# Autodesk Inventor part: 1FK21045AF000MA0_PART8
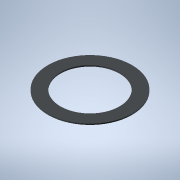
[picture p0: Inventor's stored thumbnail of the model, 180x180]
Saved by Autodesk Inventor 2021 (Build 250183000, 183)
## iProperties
Created: 2025-04
Part Number: 1FK21045AF000MA0_PART8
Material: Generic
Catalog Web Link: www.3dfindit.com
Description: -Servo synchronous motor
Document SubType Name: Modeling
Designer: psAdmin
Mass: 0.27214 g
Surface Area: 11.8752 cm^2
Volume: 0.27214 cm^3
Density: 1 g/cm^3
Appearance: PSOLRGB-212-217-219
Category: PARTsolutions
Title: 1FK21045AF000MA0_PART8
Author: Cadenas PARTsolutions
Comments: Servo synchronous motor
Sending System: PARTsolutions
Preprocessor: ST-DEVELOPER v19.3
PSOL_IDENT_0: {$CADENAS_DATA/23d-libs/siemens_ag/_cat_/8b/0a/1fk21045af000ma0.prj},213 {VTYP=3D},{NB=1FK21045AF000
PSOL_IDENT_1: MA0_PART8},{LINA=1FK21045AF000MA0_PART8},{NN=1FK21045AF000MA0_PART8},{NOPRJ=TRUE},{DATE=19.08.2025 1
PSOL_IDENT_2: 4:00:48},{GEOMDATE=30.07.2025 02:00:28},{VERSION=},{LINEID=10},{WBVAR=},{WBNUMERIC=}  {NB=1FK21045AF
PSOL_IDENT_3: 000MA0_PART8},{LINA=1FK21045AF000MA0_PART8},{KT=DUMMY},{PREVIEW=../../../_pool_/a9/69/p_d211_xx_0081
PSOL_IDENT_4: 8j.png},{DESCSHORT=SIMOTICS S-1FK2 HD, SINAMICS S210 3AC 400V-480V, 2.4 Nm, 3000 rpm},{DESCLONG=SIMO
PSOL_IDENT_5: TICS S-1FK2 HD servo motor M0=2.4 Nm; PN = 0.75 kW at nN=3000 rpm (380-480 V); PN = 0.375 kW at nN=1
PSOL_IDENT_6: 500 rpm (200-240 V); degree of protection IP64; cylindrical shaft D19x40mm; absolute encoder 22-bit
PSOL_IDENT_7: + 12-bit multiturn (encoder AM22DQC); with OCC interface; plug size M17, rotatable; SIMOTICS S-1FK2
PSOL_IDENT_8: servomotorfor a wide range of uses in industrial environments. SIMOTICS S‑1FK2 servomotors are compa
PSOL_IDENT_9: ct synchronous motors with a high dynamic performance that set themselves apart as a result of their
PSOL_IDENT_10: high power density, degree of protection and overload capability. The motors are available in two v
PSOL_IDENT_11: ariants: as High Dynamic variant (highest dynamic performance as a result of the low intrinsic momen
PSOL_IDENT_12: t of inertia for applications demanding a high dynamic performance with low moved masses) - and as C
PSOL_IDENT_13: ompact variant (precise and stable closed-loop control for medium up to large moved masses as a resu
PSOL_IDENT_14: lt of a medium intrinsic moment of inertia). SIMOTICSS‑1FK2 servomotors fully exploit their strength
PSOL_IDENT_15: s in a system with the SINAMICSS210 frequency converter and simple connection using the one cable co
PSOL_IDENT_16: nnection (OCC). Advantages include the short control and positioning times, fast and precise correct
PSOL_IDENT_17: ion of disturbing quantities as well as stable control with a high dynamic performance. The servo mo
PSOL_IDENT_18: tors can be configured to address a wide range of requirements. For example with and without holding
PSOL_IDENT_19: brake, IP64 or IP65 degree of protection, singleturn or multiturn absolute encoders - to name just
PSOL_IDENT_20: a few. Further, the servomotors are available in different shaft heights extending from 20 to 100. A
PSOL_IDENT_21: shaft sealing ring is available to achieve an IP65 degree of protection and for subsequent mounting
PSOL_IDENT_22: at the motor or as spare part. SIMOTICS - the optimum motor for each and every motion control appli
PSOL_IDENT_23: cation.},{INTNO=195125050112},{SUPPLIERALTNO=1FK2104-5AF00-0MA0},{MANUID=1FK21045AF000MA0},{MANUNAME=
PSOL_IDENT_24: Siemens},{MANUTYPEDESC=Synchronous motor 1FK2-HD 2.4 NM},{AAU732=SIMOTICS},{AAO057=S-1FK2},{AAU734=S
PSOL_IDENT_25: IMOTICS S-1FK2 HD servo motor M0=2.4 Nm; PN = 0.75 kW at nN=3000 rpm (380-480 V); PN = 0.375 kW at n
PSOL_IDENT_26: N=1500 rpm (200-240 V); degree of protection IP64; cylindrical shaft D19x40mm; absolute encoder 22-b
PSOL_IDENT_27: it + 12-bit multiturn (encoder AM22DQC); with OCC interface; plug size M17, rotatable;},{AAW338=Sync
PSOL_IDENT_28: hronous motor 1FK2-HD 2.4 NM},{AAO742=SIMOTICS},{AAO663=4042948692912},{NOCUPEROU=1},{PRICEQUANTITY=
PSOL_IDENT_29: 1},{QUANTITYMIN=1},{QUANTITYINT=1},{CTN=85015100},{COO=DE},{AAO676=1FK2104-5AF00-0MA0},{AAO677=Sieme
PSOL_IDENT_30: ns AG},{ORDERUNIT=C62},{CONTENTUNIT=C62}
NB: 1FK21045AF000MA0_PART8
NT: Servo synchronous motor
NBSYN: $MANUID._PART8
LINA: 1FK21045AF000MA0_PART8
CATALOG: SIEMENS
PREVIEW: ../../../_pool_/a9/69/p_d211_xx_00818j.png
DESCSHORT: SIMOTICS S-1FK2 HD, SINAMICS S210 3AC 400V-480V, 2.4 Nm, 3000 rpm
DESCLONG: SIMOTICS S-1FK2 HD servo motor M0=2.4 Nm; PN = 0.75 kW at nN=3000 rpm (380-480 V); PN = 0.375 kW at nN=1500 rpm (200-240 V); degree of protection IP64; cylindri
INTNO: 195125050112
SUPPLIERALTNO: 1FK2104-5AF00-0MA0
MANUID: 1FK21045AF000MA0
MANUNAME: Siemens
MANUTYPEDESC: Synchronous motor 1FK2-HD 2.4 NM
AAU732: SIMOTICS
AAO057: S-1FK2
AAU734: SIMOTICS S-1FK2 HD servo motor M0=2.4 Nm; PN = 0.75 kW at nN=3000 rpm (380-480 V); PN = 0.375 kW at nN=1500 rpm (200-240 V); degree of protection IP64; cylindri
AAW338: Synchronous motor 1FK2-HD 2.4 NM
AAO742: SIMOTICS
AAO663: 4042948692912.0
NOCUPEROU: 1
PRICEQUANTITY: 1
QUANTITYMIN: 1
QUANTITYINT: 1
CTN: 85015100
COO: DE
ARTICLENO: 1FK21045AF000MA0_PART8
BOMINFO: 1FK21045AF000MA0_PART8
CREATOR: CADENAS GmbH
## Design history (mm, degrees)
feature "2025_04_17_15_40_42_0766"
body "Solid1"
